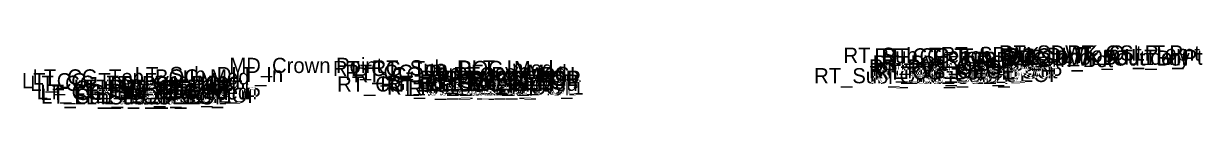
# Model space of a CAD drawing. Extents: x -26 to 6300, y -10 to 9528.
# Drawn here: x 2126 to 2203.9, y 9001.3 to 9005.5 of the extents above; entities that cross this region are included whole.
import ezdxf

# ---------------------------------------------------------------- set-up
doc = ezdxf.new("R2010")
doc.units = 0
doc.layers.add('Default', color=7, linetype='Continuous')

msp = doc.modelspace()

# ---------------------------------------------------------------- texts
at = {"layer": 'Default'}
for s, p in [('RT_Sub_Trench_Out_DLT', (2180.187, 9004.324)), ('RT_CG_Top_Face', (2182.225, 9004.284)), ('RT_CG_Top_BOC', (2182.694, 9004.284)), ('RT_SDWK_In_Top', (2186.62, 9004.374)), ('RT_SDWK_In_Bot', (2186.869, 9004.041)), ('RT_SDWK_Out_Top', (2190.462, 9004.474)), ('RT_SDWK_Out_Bot', (2190.711, 9004.141)), ('Exterior Boundary', (2192.377, 9004.197)), ('RT_CSLP_Pnt', (2194.981, 9004.474)), ('RT_Tie_Pt', (2197.539, 9004.197)), ('MD_Crown Point', (2139.582, 9003.657)), ('RT_CG_Top_BOC_Med', (2146.431, 9003.457)), ('RT_CG_Top_Face_Med', (2147.246, 9003.207)), ('RT_Sub_DLT_In', (2148.986, 9003.499)), ('RT_PV2_OEOT', (2181.873, 9003.562)), ('RT_PV3_OEOT', (2181.873, 9003.312)), ('RT_PV1_OEOT', (2182.112, 9003.812)), ('RT_CG_Bot_IE', (2182.221, 9003.229)), ('RT_CG1_Shelf_Out', (2182.36, 9003.307)), ('RT_CG_Top_Gut', (2182.752, 9003.784)), ('RT_CG_Bot_BOC', (2182.97, 9003.294)), ('LT_CG_Top_Face_Med', (2125.866, 9002.649)), ('LT_CG_Top_Gut_Med', (2126.418, 9002.482)), ('LT_CG_Top_BOC_Med', (2126.569, 9002.899)), ('LT_PV1_PGL', (2131.503, 9002.463)), ('LT_Sub_DLT_In', (2133.327, 9003.059)), ('RT_CG_Bot_BOC_Med', (2146.708, 9002.437)), ('RT_CG_Top_Gut_Med', (2147.8, 9003.04)), ('RT_CG1_Shelf_In', (2149.573, 9002.424)), ('RT_CG_Bot_IE_Med', (2149.976, 9002.476)), ('RT_PV2_OEEOP', (2152.167, 9002.81)), ('RT_PV3_OEEOP', (2152.167, 9002.56)), ('RT_PV2_IEEOP', (2152.928, 9002.81)), ('RT_PV2_PGL', (2154.145, 9002.81)), ('RT_PV1_PGL', (2154.385, 9003.06)), ('RT_Sub_OEOT_CG_1', (2178.247, 9002.979)), ('RT_Sub_OEOT', (2181.92, 9002.937)), ('RT_Sub_OEOP', (2185.155, 9003.063)), ('LT_CG_Bot_BOC_Med', (2126.846, 9001.918)), ('LT_CG_Bot_IE_Med', (2127.094, 9001.879)), ('LT_Sub_IEOT_CG_1', (2127.125, 9001.629)), ('LT_PV2_OEEOP', (2129.285, 9002.213)), ('LT_PV3_OEEOP', (2129.285, 9001.963)), ('LT_Sub_OEEOP', (2129.332, 9001.588)), ('LT_PV2_IEEOP', (2130.046, 9002.213)), ('LT_Sub_IEEOP', (2130.093, 9001.588)), ('LT_CG1_Shelf_In', (2130.711, 9001.931)), ('LT_PV2_PGL', (2131.264, 9002.213)), ('LT_Sub_PGL', (2131.311, 9001.588)), ('LT_Sub_IEOP', (2133.044, 9001.688)), ('RT_Sub_IEOT_CG_1', (2150.007, 9002.226)), ('RT_Sub_IEOP', (2151.405, 9002.167)), ('RT_Sub_OEEOP', (2152.214, 9002.185)), ('RT_Sub_IEEOP', (2152.975, 9002.185)), ('RT_Sub_PGL', (2154.192, 9002.185))]:
    msp.add_text(s, height=1, dxfattribs=at).set_placement(p)

doc.saveas('drawing.dxf')
